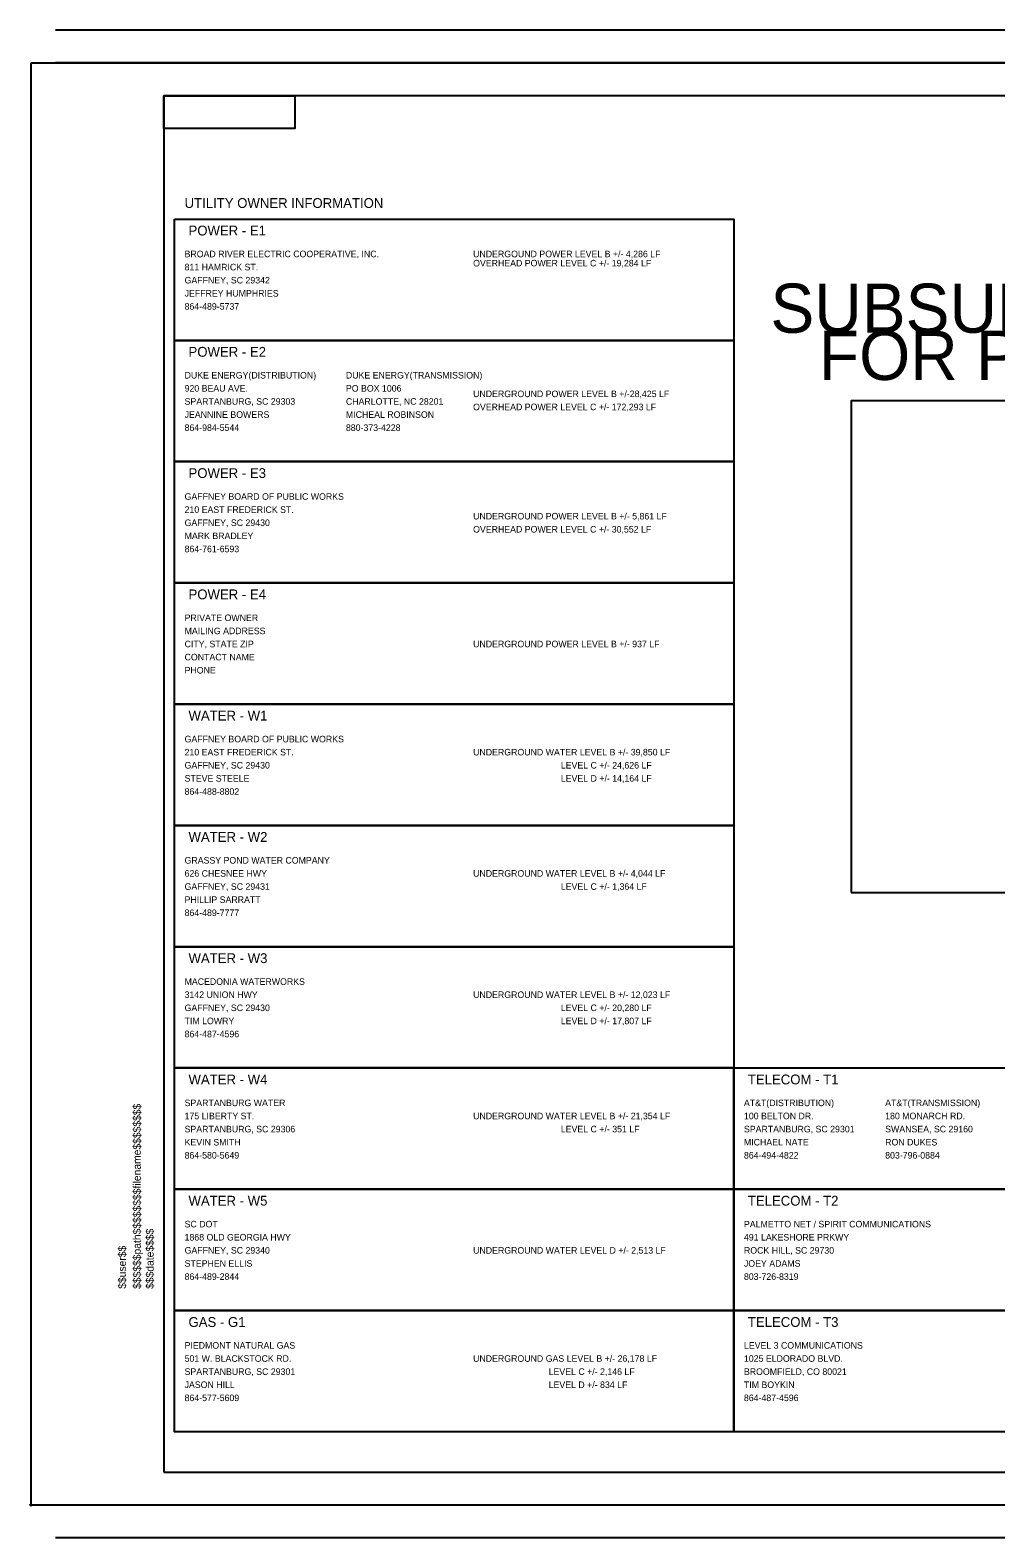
# Model space of a CAD drawing. Extents: x 189971 to 191767, y 195697 to 196847.
# Drawn here: x 189971 to 190707, y 195697 to 196847 of the extents above; entities that cross this region are included whole.
import ezdxf

# ---------------------------------------------------------------- set-up
doc = ezdxf.new("R2010")
doc.units = 0
for name, color, linetype in [('Default', 7, 'Continuous'), ('RD_SHT_Bndy', 7, 'Continuous'), ('RD_SHT_ID', 7, 'Continuous'), ('RD_SHT_Iplotshp', 7, 'Continuous'), ('RD_SHT_Snap', 7, 'Continuous'), ('RD_SHT_TX', 7, 'Continuous')]:
    doc.layers.add(name, color=color, linetype=linetype)

msp = doc.modelspace()

# ---------------------------------------------------------------- linework, layer by layer
at = {"layer": 'Default'}
msp.add_circle((189971.4, 195722.1), 0.607, dxfattribs=at)
at = {"layer": 'RD_SHT_Bndy'}
for p, q in [((191750, 196847.1), (189990, 196847.1)), ((191750, 196822.1), (189990, 196822.1)), ((191747.6, 196797.1), (190072.6, 196797.1)), ((190072.6, 196797.1), (190072.6, 195747.1)), ((190072.6, 195897.1), (190072.6, 195747.2)), ((190072.6, 195747.1), (191747.6, 195747.1)), ((191750, 195722.1), (189990, 195722.1)), ((191750, 195697.1), (189990, 195697.1))]:
    msp.add_line(p, q, dxfattribs=at)
for points in [[(190072.6, 196772.1), (190072.6, 196797.1), (190172.6, 196797.1), (190172.6, 196772.1)], [(190080.9, 196703), (190507.4, 196703), (190507.4, 196610.5), (190080.9, 196610.5)], [(190080.9, 196610.5), (190507.4, 196610.5), (190507.4, 196518), (190080.9, 196518)], [(190596.7, 196189.3), (191221.7, 196189.3), (191221.7, 196564.3), (190596.7, 196564.3)], [(190080.9, 196518), (190507.4, 196518), (190507.4, 196425.5), (190080.9, 196425.5)], [(190080.9, 196425.5), (190507.4, 196425.5), (190507.4, 196333), (190080.9, 196333)], [(190080.9, 196333), (190507.4, 196333), (190507.4, 196240.5), (190080.9, 196240.5)], [(190080.9, 196240.5), (190507.4, 196240.5), (190507.4, 196148), (190080.9, 196148)], [(190080.9, 196148), (190507.4, 196148), (190507.4, 196055.5), (190080.9, 196055.5)], [(190080.9, 196055.5), (190507.4, 196055.5), (190507.4, 195963), (190080.9, 195963)], [(190507.4, 196055.5), (190933.9, 196055.5), (190933.9, 195963), (190507.4, 195963)], [(190080.9, 195963), (190507.4, 195963), (190507.4, 195870.5), (190080.9, 195870.5)], [(190507.4, 195963), (190933.9, 195963), (190933.9, 195870.5), (190507.4, 195870.5)], [(190080.9, 195870.5), (190507.4, 195870.5), (190507.4, 195778), (190080.9, 195778)], [(190507.4, 195870.5), (190933.9, 195870.5), (190933.9, 195778), (190507.4, 195778)]]:
    msp.add_lwpolyline(points, close=True, dxfattribs=at)
at = {"layer": 'RD_SHT_Iplotshp'}
msp.add_lwpolyline([(189971.4, 196822.1), (191767.4, 196822.1), (191767.4, 195722.1), (189971.4, 195722.1)], close=True, dxfattribs=at)
at = {"layer": 'RD_SHT_Snap'}
msp.add_line((189971.4, 195722.1), (189971.4, 196822.1), dxfattribs=at)

# ---------------------------------------------------------------- texts
at = {"layer": 'Default'}
for s, p in [('SUBSURFACE UTILITY ENGINEERING', (190535.2, 196616.3)), ('FOR PROPOSED STATE HIGHWAY', (190572.2, 196580.3))]:
    msp.add_text(s, height=37.5, dxfattribs=at).set_placement(p)
at = {"layer": 'RD_SHT_ID'}
for s, p in [('$$$$$$path$$$$$$$$filename$$$$$$$$', (190055.1, 195887)), ('$$$date$$$$', (190064.9, 195887)), ('$$user$$', (190043.8, 195887.1))]:
    msp.add_text(s, height=5.88, rotation=90, dxfattribs=at).set_placement(p)
at = {"layer": 'RD_SHT_TX'}
for s, height, p in [('UTILITY OWNER INFORMATION', 7.5, (190088.5, 196711.5)), ('POWER - E1', 7.5, (190091.5, 196690.5)), ('BROAD RIVER ELECTRIC COOPERATIVE, INC.', 5, (190088.5, 196673.9)), ('UNDERGOUND POWER LEVEL B +/- 4,286 LF', 5, (190308.5, 196673.9)), ('811 HAMRICK ST.', 5, (190088.5, 196663.9)), ('OVERHEAD POWER LEVEL C +/- 19,284 LF', 5, (190308.5, 196666.9)), ('GAFFNEY, SC 29342', 5, (190088.5, 196653.9)), ('JEFFREY HUMPHRIES', 5, (190088.5, 196643.9)), ('864-489-5737', 5, (190088.5, 196633.9)), ('POWER - E2', 7.5, (190091.5, 196598)), ('DUKE ENERGY(DISTRIBUTION)', 5, (190088.5, 196581.4)), ('DUKE ENERGY(TRANSMISSION)', 5, (190211.5, 196581.4)), ('920 BEAU AVE.', 5, (190088.5, 196571.4)), ('PO BOX 1006', 5, (190211.5, 196571.4)), ('UNDERGROUND POWER LEVEL B +/-28,425 LF', 5, (190308.5, 196567.2)), ('SPARTANBURG, SC 29303', 5, (190088.5, 196561.4)), ('CHARLOTTE, NC 28201', 5, (190211.5, 196561.4)), ('OVERHEAD POWER LEVEL C +/- 172,293 LF', 5, (190308.5, 196557.2)), ('JEANNINE BOWERS', 5, (190088.5, 196551.4)), ('MICHEAL ROBINSON', 5, (190211.5, 196551.4)), ('864-984-5544', 5, (190088.5, 196541.4)), ('880-373-4228', 5, (190211.5, 196541.4)), ('POWER - E3', 7.5, (190091.5, 196505.5)), ('GAFFNEY BOARD OF PUBLIC WORKS', 5, (190088.5, 196488.9)), ('210 EAST FREDERICK ST.', 5, (190088.5, 196478.9)), ('UNDERGROUND POWER LEVEL B +/- 5,861 LF', 5, (190308.5, 196473.9)), ('GAFFNEY, SC 29430', 5, (190088.5, 196468.9)), ('OVERHEAD POWER LEVEL C +/- 30,552 LF', 5, (190308.5, 196463.9)), ('MARK BRADLEY', 5, (190088.5, 196458.9)), ('864-761-6593', 5, (190088.5, 196448.9)), ('POWER - E4', 7.5, (190091.5, 196413)), ('PRIVATE OWNER', 5, (190088.5, 196396.4)), ('MAILING ADDRESS', 5, (190088.5, 196386.4)), ('CITY, STATE ZIP', 5, (190088.5, 196376.4)), ('UNDERGROUND POWER LEVEL B +/- 937 LF', 5, (190308.5, 196376.4)), ('CONTACT NAME', 5, (190088.5, 196366.4)), ('PHONE', 5, (190088.5, 196356.4)), ('WATER - W1', 7.5, (190091.5, 196320.5)), ('GAFFNEY BOARD OF PUBLIC WORKS', 5, (190088.5, 196303.9)), ('210 EAST FREDERICK ST.', 5, (190088.5, 196293.9)), ('UNDERGROUND WATER LEVEL B +/- 39,850 LF', 5, (190308.5, 196293.9)), ('GAFFNEY, SC 29430', 5, (190088.5, 196283.9)), ('                                    LEVEL C +/- 24,626 LF', 5, (190308.5, 196283.9)), ('STEVE STEELE', 5, (190088.5, 196273.9)), ('                                    LEVEL D +/- 14,164 LF', 5, (190308.5, 196273.9)), ('864-488-8802', 5, (190088.5, 196263.9)), ('WATER - W2', 7.5, (190091.5, 196228)), ('GRASSY POND WATER COMPANY', 5, (190088.5, 196211.4)), ('626 CHESNEE HWY', 5, (190088.5, 196201.4)), ('UNDERGROUND WATER LEVEL B +/- 4,044 LF', 5, (190308.5, 196201.4)), ('GAFFNEY, SC 29431', 5, (190088.5, 196191.4)), ('                                    LEVEL C +/- 1,364 LF', 5, (190308.5, 196191.4)), ('PHILLIP SARRATT', 5, (190088.5, 196181.4)), ('864-489-7777', 5, (190088.5, 196171.4)), ('WATER - W3', 7.5, (190091.5, 196135.5)), ('MACEDONIA WATERWORKS', 5, (190088.5, 196118.9)), ('3142 UNION HWY', 5, (190088.5, 196108.9)), ('UNDERGROUND WATER LEVEL B +/- 12,023 LF', 5, (190308.5, 196108.9)), ('GAFFNEY, SC 29430', 5, (190088.5, 196098.9)), ('                                    LEVEL C +/- 20,280 LF', 5, (190308.5, 196098.9)), ('TIM LOWRY', 5, (190088.5, 196088.9)), ('                                    LEVEL D +/- 17,807 LF', 5, (190308.5, 196088.9)), ('864-487-4596', 5, (190088.5, 196078.9)), ('WATER - W4', 7.5, (190091.5, 196043)), ('TELECOM - T1', 7.5, (190518, 196043)), ('SPARTANBURG WATER', 5, (190088.5, 196026.4)), ('AT&T(DISTRIBUTION)', 5, (190515, 196026.4)), ('AT&T(TRANSMISSION)', 5, (190622.7, 196026.4)), ('175 LIBERTY ST.', 5, (190088.5, 196016.4)), ('UNDERGROUND WATER LEVEL B +/- 21,354 LF', 5, (190308.5, 196016.4)), ('100 BELTON DR.', 5, (190515, 196016.4)), ('180 MONARCH RD.', 5, (190622.7, 196016.4)), ('SPARTANBURG, SC 29306', 5, (190088.5, 196006.4)), ('                                    LEVEL C +/- 351 LF', 5, (190308.5, 196006.4)), ('SPARTANBURG, SC 29301', 5, (190515, 196006.4)), ('SWANSEA, SC 29160', 5, (190622.7, 196006.4)), ('KEVIN SMITH', 5, (190088.5, 195996.4)), ('MICHAEL NATE', 5, (190515, 195996.4)), ('RON DUKES', 5, (190622.7, 195996.4)), ('864-580-5649', 5, (190088.5, 195986.4)), ('864-494-4822', 5, (190515, 195986.4)), ('803-796-0884', 5, (190622.7, 195986.4)), ('WATER - W5', 7.5, (190091.5, 195950.5)), ('TELECOM - T2', 7.5, (190518, 195950.5)), ('SC DOT', 5, (190088.5, 195933.9)), ('PALMETTO NET / SPIRIT COMMUNICATIONS', 5, (190515, 195933.9)), ('1868 OLD GEORGIA HWY', 5, (190088.5, 195923.9)), ('491 LAKESHORE PRKWY', 5, (190515, 195923.9)), ('GAFFNEY, SC 29340', 5, (190088.5, 195913.9)), ('UNDERGROUND WATER LEVEL D +/- 2,513 LF', 5, (190308.5, 195913.9)), ('ROCK HILL, SC 29730', 5, (190515, 195913.9)), ('STEPHEN ELLIS', 5, (190088.5, 195903.9)), ('JOEY ADAMS', 5, (190515, 195903.9)), ('864-489-2844', 5, (190088.5, 195893.9)), ('803-726-8319', 5, (190515, 195893.9)), ('GAS - G1', 7.5, (190091.5, 195858)), ('TELECOM - T3', 7.5, (190518, 195858)), ('PIEDMONT NATURAL GAS', 5, (190088.5, 195841.4)), ('LEVEL 3 COMMUNICATIONS', 5, (190515, 195841.4)), ('501 W. BLACKSTOCK RD.', 5, (190088.5, 195831.4)), ('UNDERGROUND GAS LEVEL B +/- 26,178 LF', 5, (190308.5, 195831.4)), ('1025 ELDORADO BLVD.', 5, (190515, 195831.4)), ('SPARTANBURG, SC 29301', 5, (190088.5, 195821.4)), ('                               LEVEL C +/- 2,146 LF', 5, (190308.5, 195821.4)), ('BROOMFIELD, CO 80021', 5, (190515, 195821.4)), ('JASON HILL', 5, (190088.5, 195811.4)), ('                               LEVEL D +/- 834 LF', 5, (190308.5, 195811.4)), ('TIM BOYKIN', 5, (190515, 195811.4)), ('864-577-5609', 5, (190088.5, 195801.4)), ('864-487-4596', 5, (190515, 195801.4))]:
    msp.add_text(s, height=height, dxfattribs=at).set_placement(p)

doc.saveas('drawing.dxf')
